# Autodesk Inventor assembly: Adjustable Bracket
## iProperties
Shininess: 50.0
Length Units: 11272
Angle Units: 11279
Time Units: 11290
Mass Units: 11286
Length Display Precision: 4
Angle Display Precision: 2
Compacted: True
Company: Autodesk
Manager: Lebovitz
Created: 2000-11
Part Number: Adjustable Bracket
Document SubType Name: Assembly
Designer: The PD Team
Project: Inventor Samples
Checked By: The PD Team
Description: Adjustable Bracket
Density: 0.0
Volumn: 0.0
Area: 0.0
PropertySet Name: Model Information
Control State: 0
Master: False
Checked Out: False
Author: The PD Team
Title: Bracket Sample
Subject: Inventor Samples
Revision Number: A
